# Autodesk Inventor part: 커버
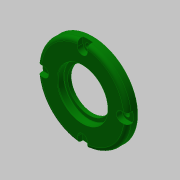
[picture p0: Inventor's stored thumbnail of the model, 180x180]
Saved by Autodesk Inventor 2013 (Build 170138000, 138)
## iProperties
Created: 2019-05
Part Number: 커버
Material: 알루미늄 6061
Document SubType Name: Modeling
Designer: mduedu
Density: 1 g/cm^3
d0: 72.000 mm
d2: 52.000 mm
d3: 12.000 mm
d4: 4.000 mm
d6: 62.000 mm
d7: 8.000 mm
d8: 4.400 mm
d9: 0.00 deg
d10: 4.000 ul
d11: 360.00 deg
d13: 3.000 mm
d14: 40.000 mm
d16: 5.200 mm
d17: 46.000 mm
d18: 4.000 mm
d19: 34.000 mm
d21: 0.500 mm
d23: 30.00 deg
d24: 0.200 mm
d25: 3.000 mm
d26: 1.000 mm
d29: 62.000 mm
d30: 4.000 ul
d34: 4.500 mm
d32: 360.00 deg
Author: mduedu
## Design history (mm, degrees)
sketch "스케치1"
  geometry: L1 (0, 0)-(36, 0); L2 (36, 0)-(36, -8); L3 (36, -8)-(0, -8); L4 (0, -8)-(0, 0); L5 (0, -8)-(26, -8); L6 (26, -8)-(26, -12); L7 (26, -12)-(0, -12); L8 (0, -12)-(0, -8)
  constraints: 16 end point, 4 parallel, 2 horizontal, 2 perpendicular
  dimensions: "d0" = 72 diameter of L2 L4; "d2" = 52 diameter of L6 L8; "d3" = 12 distance between parallel lines of L7 L1; "d4" = 4 distance between parallel lines of L7 L3
revolve "회전1" sketch "스케치1" stored, may be unused: angle "d5" = 90 deg
sketch "스케치2" dims "d6" = 62
  geometry: L1 (-4, 31)-(-4, 35.777); L2 (4, 31)-(4, 35.777); A1 r 4 centre (0, 31) between (-4, 31) and (4, 31); A2 r 36 centre (0, 0) between (-4, 35.777) and (4, 35.777) reference; A3 r 36 centre (0, 0) between (4, 35.777) and (-4, 35.777); 2 further points
  constraints: 6 point on circle, 4 end point, 2 centre point, 2 coincident, 2 tangent, 2 vertical alignment, 1 parallel, 1 vertical, 2 other
  dimensions: "d7" = 8 distance between parallel lines of L2 L1
extrude "돌출1" cut sketch "스케치2" distance "d8" = 4.4; taper "d9" = 0 deg
fillet "모깎기1" dims "d13" = 3
sketch "스케치3"
  geometry: L1 (36, -4.4)-(36, -8) reference; L2 (36, -8)-(26, -8) reference; L3 (26, -8)-(26, -12) reference; L4 (26, -12)-(-26, -12) reference; L5 (-26, -12)-(-26, -8) reference; L6 (-26, -8)-(-36, -8) reference; L7 (-36, -8)-(-36, -4.4) reference; L8 (-36, -4.4)-(-27, -4.4) reference; L9 (-27, -4.4)-(-27, 0) reference; L10 (-27, 0)-(27, 0) reference; L11 (27, 0)-(27, -4.4) reference; L12 (27, -4.4)-(36, -4.4) reference; L13 (0, 0)-(20, 0); L14 (20, 0)-(20, -5.2); L15 (20, -5.2)-(0, -5.2); L16 (0, -5.2)-(0, 0); L17 (0, -5.2)-(17, -5.2); L18 (17, -5.2)-(17, -8); L19 (17, -8)-(0, -8); L20 (0, -8)-(0, -5.2); L21 (0, -8)-(23, -8); L22 (23, -8)-(23, -12); L23 (23, -12)-(0, -12); L24 (0, -12)-(0, -8)
  constraints: 24 end point, 6 parallel, 3 horizontal, 3 perpendicular, 1 point on line
  dimensions: "d14" = 40 diameter of L14 L16; "d16" = 5.2 distance of L13.end L14.end; "d17" = 46 diameter of L22 L24; "d18" = 4 distance of L21.end L22.end; "d19" = 34 diameter of L18 L20
revolve "회전2" sketch "스케치3" stored, may be unused: angle "d20" = 90 deg
chamfer "모따기1" distance "d21" = 0.5; stored, may be unused: second distance "d22" = 2, angle "d23" = 30 deg
fillet "모깎기2" dims "d24" = 0.2
fillet "모깎기3" dims "d25" = 3
chamfer "모따기2" distance "d26" = 1; stored, may be unused: second distance "d27" = 2, angle "d28" = 30 deg
sketch "스케치4" dims "d29" = 62
  geometry: 6 further points
  constraints: 2 vertical alignment, 1 coincident, 7 other
  dimensions: "d32" = 360 deg dimension on point (0, 0) point (0, 31) (derived)
sketch "스케치5"
  geometry: 4 further points
  constraints: 4 other
hole "구멍1" sketch "스케치5" at (-31, 0), (0, -31), (31, 0), (0, 31) diameter "d34" = 4.5; stored, may be unused: countersink angle "d38" = 90 deg, drill point angle "d40" = 0 deg; dims "d35" = 6, "d36" = 4, "d37" = 2, "d39" = 8
node "솔리드1"
pattern_circular "원형 패턴1" dims count "d10" = 4, angle "d11" = 360 deg
node "절단 모서리 투영1"
other parameters: "d30" = 4
